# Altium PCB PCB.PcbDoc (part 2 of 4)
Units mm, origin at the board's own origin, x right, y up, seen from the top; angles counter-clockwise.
Board outline 114 x 86.5 mm, 4 copper layers (TOP, GND, SIG, BOTTOM), stack 1.586 mm thick; 98 components, 195 nets, 719 pads, 522 vias.
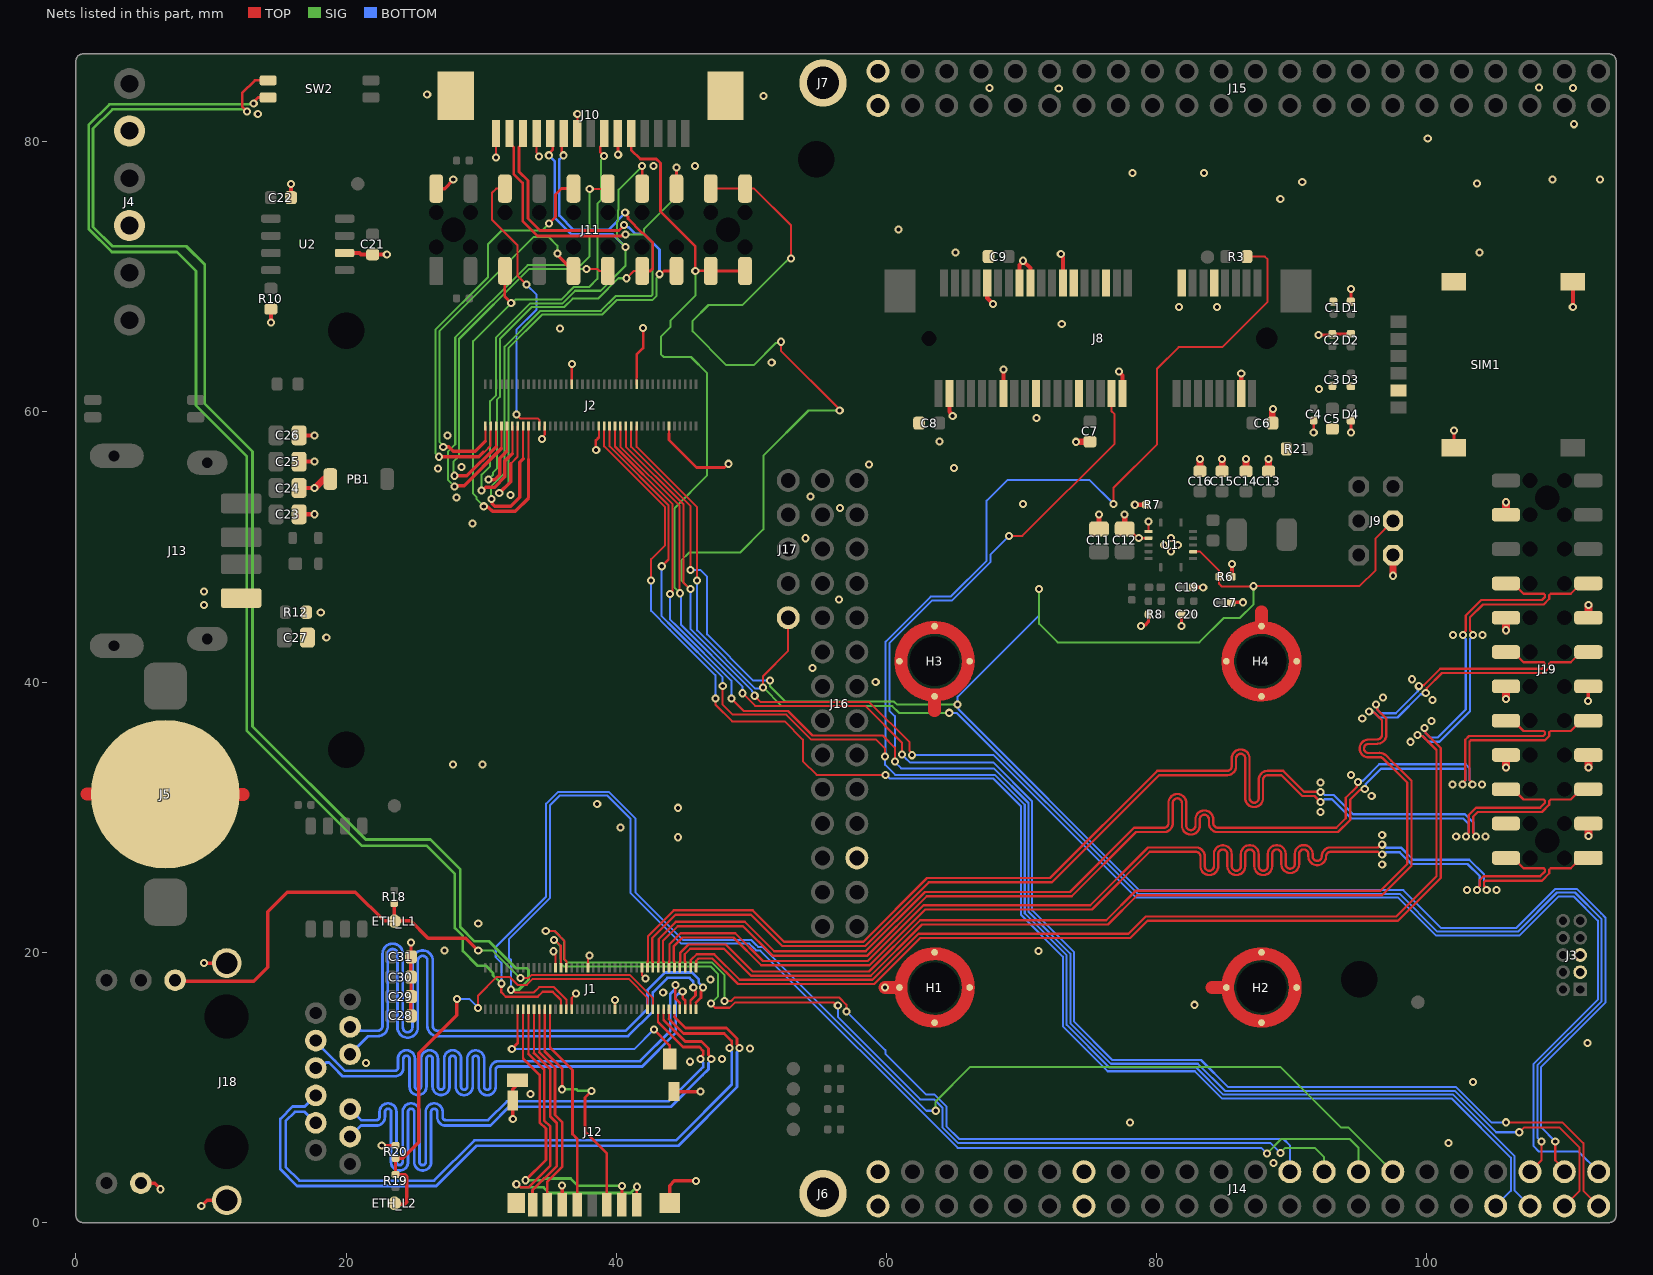
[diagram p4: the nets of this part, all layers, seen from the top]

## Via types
v1: diameter 0.6, hole 0.3, TOP to BOTTOM, tented both sides, 522 vias

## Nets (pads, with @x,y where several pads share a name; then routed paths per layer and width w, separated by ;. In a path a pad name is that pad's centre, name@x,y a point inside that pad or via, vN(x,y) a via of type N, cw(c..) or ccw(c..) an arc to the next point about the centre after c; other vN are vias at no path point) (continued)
CAM.CK_1_P: J2.18 J10.9 J11.5 | length 46.6
  TOP w0.15: 33.5,56.506 J2.18@33.5,58.96
  TOP w0.2: J11.5@31.75,70.435 31.75,68.529 v1(32.218,68.061) ; v1(39.078,78.953) 39.078,78.962 38.8,79.24 38.8,79.605 39.1,79.905 J10.9@39.1,80.6
  TOP w0.25: v1(30.185,53.018) 30.252,52.951 30.528,52.951 30.832,52.647 32.516,52.647 33.5,53.631 33.5,56.506
  SIG w0.15: v1(30.185,53.018) 29.633,53.57 29.633,53.722 29.404,53.951 29.404,65.247 v1(32.218,68.061) 32.264,68.061 32.524,68.321 35.908,68.321 36.837,69.25 38,69.25 38.6,69.849 38.6,75.425 38.852,75.678 38.852,78.64 39.078,78.866 v1(39.078,78.953)
CAM.D0_1_N: J2.16 J10.2 J11.16 | length 61
  TOP w0.15: 33.1,56.548 J2.16@33.1,58.96
  TOP w0.2: J10.2@32.1,80.6 32.1,79.905 32.4,79.605 32.4,77.617 33.062,76.955 33.062,74.148 34.178,73.032 40.359,73.032 40.386,73.059 40.603,73.059 v1(40.677,73.132) ; J11.16@44.45,76.535 44.454,76.539 44.454,78.095 v1(44.457,78.099)
  TOP w0.25: v1(30.749,53.57) 30.816,53.503 30.816,53.196 30.988,53.024 32.18,53.024 32.838,53.682 32.838,56.286 33.1,56.548
  SIG w0.15: v1(30.749,53.57) 30.737,53.582 30.737,54.486 31.73,55.48 31.73,64.833 34.387,67.49 38.851,67.49 39.936,68.574 42.566,68.574 42.687,68.696 42.687,72.502 42.054,73.135 ; v1(40.677,73.132) 40.68,73.135 42.054,73.135 ; v1(44.457,78.099) 44.457,75.957 42.054,73.554 42.054,73.135
CAM.D0_1_P: J2.14 J10.3 J11.15 | length 51.7
  TOP w0.15: 32.175,56.176 32.7,56.701 J2.14@32.7,58.96
  TOP w0.2: J10.3@33.1,80.6 33.1,79.905 32.8,79.605 32.8,77.783 33.462,77.121 33.462,74.313 34.344,73.432 40.196,73.432 40.568,73.804 v1(40.568,73.851) ; v1(43.196,70.196) 43.283,70.196 43.522,70.435 J11.15@44.45,70.435
  TOP w0.25: v1(31.333,54.002) 32.175,54.844 32.175,56.176
  SIG w0.15: v1(31.333,54.002) 32.007,54.677 32.007,64.718 34.502,67.213 38.966,67.213 40.05,68.297 42.68,68.297 42.964,68.581 42.964,69.883 43.196,70.115 v1(43.196,70.196)
  BOTTOM w0.2: v1(40.568,73.851) 40.676,73.851 40.865,73.662 40.926,73.662 41.402,73.187 42.038,73.187 43.202,72.022 43.202,70.202 v1(43.196,70.196)
CAM.D1_1_N: J2.12 J10.5 J11.14 | length 52.4
  TOP w0.15: 32.303,56.921 J2.12@32.303,58.946
  TOP w0.2: v1(35,79) 35.077,79.077 35.077,79.195 35.298,79.417 35.298,79.707 35.1,79.905 J10.5@35.1,80.6 ; J11.14@41.91,76.535 v1(41.91,78.2)
  TOP w0.25: v1(30.021,54.201) 30.108,54.201 30.347,54.44 30.99,54.44 31.752,55.202 31.752,56.369 32.303,56.921
  SIG w0.15: v1@30.031,54.21 30.031,55.357 30.657,55.983 30.657,60.797 31.1,61.24 31.1,65.515 33.629,68.044 36.023,68.044 36.952,68.973 38.833,68.973 40.676,70.816 v1(40.676,72.215) 40.066,72.826 40.066,74.059 40.122,74.115 40.122,74.931 40.174,74.984 40.174,76.464 v1(41.91,78.2)
  BOTTOM w0.2: v1(35,79) 35.434,78.566 35.434,74.387 36.685,73.135 39.756,73.135 v1(40.676,72.215)
CAM.D1_1_P: J2.10 J10.6 J11.13 | length 46.2
  TOP w0.15: 31.9,57.103 J2.10@31.9,58.96 ; v1(40.759,69.898) 41.296,70.435 J11.13@41.91,70.435
  TOP w0.2: v1(36.1,79) 36.1,79.108 35.953,79.256 35.953,80.453 J10.6@36.1,80.6 ; v1(40.656,74.755) 40.656,74.647 40.856,74.447 40.856,74.308 41.903,73.261 41.963,73.261 42.687,72.537 42.687,70.602 42.52,70.435 J11.13@41.91,70.435
  TOP w0.25: v1(30.533,54.992) 31.009,54.992 31.375,55.358 31.375,56.578 31.9,57.103
  SIG w0.15: v1(30.533,54.992) 30.533,55.017 30.853,55.337 30.853,55.496 31.159,55.802 31.159,60.907 31.377,61.125 31.377,65.401 33.743,67.767 36.138,67.767 36.764,68.393 38.645,68.393 40.15,69.898 v1(40.759,69.898)
  BOTTOM w0.2: v1(36.1,79) 35.784,78.684 35.784,74.532 36.83,73.485 39.406,73.485 40.656,74.735 v1(40.656,74.755)
CAM.D2_1_N: J2.8 J11.12 | length 36.5
  TOP w0.15: 31.5,57.303 J2.8@31.5,58.96 ; v1(38.029,76.49) 39.324,76.49 J11.12@39.37,76.535
  TOP w0.25: v1(28.029,54.473) 28.096,54.54 28.737,54.54 31.5,57.303
  SIG w0.15: v1(28.029,54.473) 27.527,54.975 27.527,57.05 28.076,57.599 28.076,65.517 33.429,70.87 37.372,70.87 38.029,71.528 v1(38.029,76.49)
CAM.D2_1_P: J2.6 J11.11 | length 29.1
  TOP w0.15: 31.1,57.436 J2.6@31.1,58.96 ; v1(37.805,70.593) 38.597,70.593 38.755,70.435 J11.11@39.37,70.435
  TOP w0.25: v1(28.029,55.28) 28.944,55.28 31.1,57.436
  SIG w0.15: v1(28.029,55.28) 27.943,55.366 27.943,55.586 27.937,55.593 27.937,56.305 28.353,56.722 28.353,65.403 33.544,70.593 v1(37.805,70.593)
CAM.D3_1_N: J2.4 J11.10 | length 32.1
  TOP w0.15: 30.159,57.028 30.211,57.028 30.7,57.517 J2.4@30.7,58.96
  TOP w0.2: v1(35.029,73.959) 35.5,74.43 35.5,76.1 35.935,76.535 J11.10@36.83,76.535
  TOP w0.25: v1(26.887,56.685) 29.816,56.685 30.159,57.028
  SIG w0.15: v1(26.887,56.685) 26.61,56.962 26.61,66.076 30.5,69.966 30.5,72.41 31.521,73.432 34.502,73.432 v1(35.029,73.959)
CAM.D3_1_P: J2.2 J11.9 | length 27.6
  TOP w0.15: 30.3,57.832 J2.2@30.3,58.96
  TOP w0.25: v1(27.188,57.42) 27.588,57.42 27.929,57.078 29.546,57.078 30.3,57.832 ; v1(35.634,71.717) 35.634,71.631 J11.9@36.83,70.435
  SIG w0.15: v1(27.188,57.42) 27.188,57.519 26.902,57.804 26.902,65.976 33.893,72.967 34.979,72.967 35.634,72.313 v1(35.634,71.717)
CAM.HS_1: J2.22 J11.6 | length 21.8
  TOP w0.15: J11.6@31.75,76.535 31.1,76.535 30.795,76.23 30.795,74.234 32.684,72.345 32.684,70.091 v1(33.353,69.423) ; v1(32.598,59.816) 32.896,59.518 33.648,59.518 33.65,59.516 34.194,59.516 34.3,59.41 J2.22@34.3,58.96
  BOTTOM w0.15: v1(32.598,59.816) 32.598,66.072 34.073,67.547 34.073,68.702 v1(33.353,69.423)
CAN0.RX_1: J1.52 J14.28 | length 71.8
  TOP w0.15: v1(35.372,20.926) 35.455,20.926 35.886,20.495 35.886,19.519 35.9,19.505 J1.52@35.9,18.86 ; v1(47,16.2) 47.302,15.898 48.388,15.898 48.792,16.302 56.074,16.302 56.32,16.056 v1(56.393,16.056)
  SIG w0.15: v1(35.372,20.926) 35.86,20.438 35.86,19.194 36.094,18.96 46.97,18.96 47.519,18.412 47.519,16.719 v1(47,16.2) ; v1(89.156,5.16) 89.52,5.524 91.694,5.524 92.394,4.824 J14.28@92.394,3.76
  BOTTOM w0.15: v1(56.393,16.056) 56.393,15.217 62.493,9.117 63.515,9.117 64.153,8.48 64.153,7.027 65.276,5.904 88.412,5.904 v1(89.156,5.16)
CAN0.TX_1: J1.50 J14.26 | length 70.8
  TOP w0.15: v1(34.773,21.585) 35.423,21.585 35.874,21.134 35.874,21.123 36.163,20.834 36.163,19.634 36.18,19.617 36.18,19.478 36.3,19.357 J1.50@36.3,18.86 ; v1(48,16.4) 48.498,16.4 48.739,16.641 56.518,16.641 57.03,16.129 v1(57.03,15.634)
  SIG w0.15: v1(34.773,21.585) 35.423,21.585 36.14,20.867 36.14,19.469 36.372,19.237 47.085,19.237 48.021,18.302 48.021,16.421 v1(48,16.4)
  BOTTOM w0.15: v1(57.03,15.634) 59.908,12.755 59.908,12.482 62.931,9.46 63.564,9.46 64.43,8.594 64.43,7.142 65.39,6.181 89.383,6.181 89.854,5.71 J14.26@89.854,3.76
CAN1.RX_1: J1.51 J14.32 SW2.2 | length 198.7
  TOP w0.15: 35.868,16.505 35.9,16.473 J1.51@35.9,15.78
  TOP w0.18: v1(31.487,17.677) 31.487,17.044 31.817,16.714 34.178,16.714 34.55,17.086 35.286,17.086 35.868,16.505
  TOP w0.2: v1(13.157,82.829) 13.234,82.905 13.234,83.026 13.482,83.274 SW2.2@14.217,83.274
  SIG w0.15: v1(63.642,8.274) 63.642,8.956 66.212,11.526 89.156,11.526 93.661,7.021 94.213,7.021 J14.32@97.474,3.76
  SIG w0.2: v1(13.157,82.829) 13.1,82.772 2.477,82.772 0.936,81.231 0.936,73.56 2.655,71.84 7.481,71.84 8.888,70.434 8.888,60.476 12.633,56.73 12.633,36.417 21.15,27.9 25.95,27.9 28.047,25.803 28.047,21.796 28.633,21.209 28.633,20.083 29.705,19.012 30.335,19.012 30.873,18.474 30.873,18.291 v1(31.487,17.677)
  BOTTOM w0.15: v1(31.487,17.677) 31.487,19.235 31.073,19.649 31.073,20.395 34.81,24.132 34.81,31.01 35.685,31.885 39.438,31.885 41.406,29.917 41.406,24.435 44.924,20.917 49.966,20.917 50.305,20.578 50.319,20.578 50.492,20.405 50.813,20.405 62.945,8.274 v1(63.642,8.274)
CAN1.TX_1: J1.49 J14.30 SW2.1 | length 198.2
  TOP w0.15: v1(32.195,17.231) 32.316,17.231 32.505,17.042 33.905,17.042 34.285,17.423 35.384,17.423 36.3,16.507 J1.49@36.3,15.78
  TOP w0.2: v1(12.66,82.245) 12.302,82.603 12.302,83.607 13.24,84.544 SW2.1@14.217,84.544
  SIG w0.15: v1(88.15,5.102) 89.228,6.181 94.277,6.181 94.934,5.524 J14.30@94.934,3.76
  SIG w0.2: v1(12.66,82.245) 12.552,82.245 12.395,82.402 2.697,82.402 1.264,80.968 1.264,73.694 2.69,72.268 8.164,72.268 9.536,70.896 9.536,60.597 13.075,57.059 13.075,36.725 21.45,28.35 26.229,28.35 28.448,26.13 28.448,21.856 29.489,20.816 30.592,20.816 32.592,18.816 33.383,18.816 33.5,18.699 33.5,17.953 32.778,17.231 v1(32.195,17.231)
  BOTTOM w0.15: v1(32.195,17.231) 32.195,19.465 32.044,19.615 32.044,20.974 35.1,24.03 35.1,30.908 35.8,31.608 39.323,31.608 41.063,29.869 41.063,24.387 44.809,20.64 49.851,20.64 50.19,20.301 50.204,20.301 50.377,20.128 50.66,20.128 65.264,5.524 87.728,5.524 v1(88.15,5.102)
CD: J1.67 J12.CD1 | length 16.9
  TOP w0.15: 32.7,13.664 J1.67@32.7,15.78
  TOP w0.2: v1(32.262,12.833) 32.7,13.272 32.7,13.664 ; v1(42.777,14.29) 43.95,13.117 J12.CD1@43.95,12.112
  BOTTOM w0.15: v1(32.262,12.833) 41.32,12.833 v1(42.777,14.29)
CLK: J1.55 J12.5 | length 15.3
  TOP w0.15: 35.1,12.953 J1.55@35.1,15.78
  TOP w0.2: 35.1,12.953 36.761,11.292 36.761,6.542 37.1,6.203 J12.5@37.1,1.312
CMD: J1.57 J12.3 | length 18
  TOP w0.15: 34.7,12.661 J1.57@34.7,15.78
  TOP w0.2: 34.7,12.661 36,11.361 36,9.88 v1(35.982,9.862) ; v1(38.175,9.75) 38.161,9.75 37.673,9.262 37.673,6.734 39.3,5.107 J12.3@39.3,1.312
  SIG w0.2: v1(35.982,9.862) 37.058,9.862 37.17,9.75 v1(38.175,9.75)
D0: J1.59 J12.7 | length 15.6
  TOP w0.15: 34.3,12.599 J1.59@34.3,15.78
  TOP w0.2: 34.3,12.599 35.455,11.444 35.455,7.954 36,7.408 36,4.134 34.876,3.01 34.876,1.336 J12.7@34.9,1.312
D1: J1.61 J12.8 | length 15.9
  TOP w0.15: 33.9,12.536 J1.61@33.9,15.78
  TOP w0.2: J12.8@33.8,1.312 33.8,2.396 35.597,4.193 35.597,7.35 35.115,7.831 35.115,11.321 33.9,12.536
D2: J1.63 J12.1 | length 26.3
  TOP w0.15: 33.5,12.474 J1.63@33.5,15.78
  TOP w0.2: v1(32.594,2.832) 32.697,2.832 32.928,2.601 33.506,2.601 35.115,4.209 35.115,7.093 34.653,7.555 34.653,11.321 33.5,12.474 ; J12.1@41.5,1.312 41.519,1.331 v1(41.519,2.649)
  SIG w0.2: v1(32.594,2.832) 32.697,2.832 32.928,2.601 34.606,2.601 35.019,2.188 41.058,2.188 v1(41.519,2.649)
D3: J1.65 J12.2 | length 22.8
  TOP w0.15: 33.1,12.153 J1.65@33.1,15.78
  TOP w0.2: 33.1,12.153 34.326,10.927 34.326,7.42 34.788,6.958 34.788,4.628 v1(33.288,3.128) ; J12.2@40.4,1.312 40.418,1.33 v1(40.418,2.715)
  SIG w0.2: v1(33.288,3.128) 34.541,3.128 34.671,3.258 36.616,3.258 37.16,2.715 v1(40.418,2.715)
DSI_CK_N: J1.20 J19.5 | length 90.9
  TOP w0.17: J1.20@42.3,18.86 42.3,19.324 42.34,19.364 42.34,21.193 44.254,23.106 50.096,23.106 52.41,20.792 58.293,20.792 62.999,25.498 72.106,25.498 80.041,33.433 84.971,33.433 85.216,33.433 ccw(c85.216,33.772) 85.555,33.772 85.555,34.363 cw(c86.214,34.363) 86.873,34.363 86.873,31.411 ccw(c87.212,31.411) 87.551,31.411 87.551,32.774 cw(c88.21,32.774) 88.21,33.433 89.365,33.433 90.912,31.886 91.102,31.886 92.096,31.886 v1(92.126,31.856) ; v1(103.624,28.561) 103.624,28.672 103.42,28.876 103.42,30.041 103.763,30.384 108.514,30.384 109.064,30.935 109.064,31.208 109.164,31.307 110.652,31.307 111.414,32.069 J19.5@111.954,32.069
  BOTTOM w0.17: v1(92.126,31.856) 92.237,31.856 92.44,31.653 93.107,31.653 94.53,30.23 102.823,30.23 103.42,29.633 103.42,28.881 103.624,28.678 v1(103.624,28.561)
DSI_CK_P: J1.18 J19.6 | length 90
  TOP w0.17: J1.18@42.7,18.86 42.7,19.324 42.66,19.364 42.66,21.06 44.386,22.786 49.963,22.786 52.277,20.472 58.426,20.472 63.131,25.178 72.238,25.178 80.173,33.113 84.971,33.113 85.216,33.113 ccw(c85.216,33.772) 85.875,33.772 85.875,34.363 cw(c86.214,34.363) 86.553,34.363 86.553,31.411 ccw(c87.212,31.411) 87.871,31.411 87.871,32.774 cw(c88.21,32.774) 88.21,33.113 89.232,33.113 90.779,31.566 91.102,31.566 91.689,31.566 92.015,31.24 92.015,31.129 v1(92.126,31.129) ; v1(102.897,28.561) 102.897,28.672 103.1,28.876 103.1,30.174 103.631,30.704 108.381,30.704 108.744,31.067 108.744,31.208 108.644,31.307 107.156,31.307 106.394,32.069 J19.6@105.854,32.069
  BOTTOM w0.17: v1(92.126,31.129) 92.237,31.129 92.44,31.333 92.975,31.333 94.397,29.91 102.69,29.91 103.1,29.5 103.1,28.881 102.897,28.678 v1(102.897,28.561)
DSI_D0_N: J1.16 J19.9 | length 90.9
  TOP w0.17: J1.16@43.1,18.86 43.1,19.324 43.14,19.364 43.14,20.993 44.406,22.259 49.509,22.259 51.69,20.078 58.452,20.078 62.847,24.473 73.579,24.473 78.328,29.222 80.287,29.222 80.532,29.222 ccw(c80.532,29.561) 80.871,29.561 80.871,31.059 cw(c81.53,31.059) 82.189,31.059 82.189,29.377 ccw(c82.528,29.377) 82.867,29.377 82.867,29.849 cw(c83.526,29.849) 84.185,29.849 84.185,29.561 ccw(c84.524,29.561) 84.524,29.222 85.985,29.222 93.292,29.222 94,29.931 94,31.44 94.807,32.248 94.807,32.536 v1(94.886,32.614) ; v1(103.36,32.417) 103.36,32.528 103.156,32.731 103.156,35.6 103.256,35.699 108.749,35.699 109.064,36.015 109.064,36.288 109.164,36.387 110.652,36.387 111.414,37.149 J19.9@111.954,37.149
  BOTTOM w0.17: v1(94.886,32.614) 94.964,32.693 95.252,32.693 96.48,33.92 102.87,33.92 103.157,33.633 103.157,32.731 103.36,32.528 v1(103.36,32.417)
DSI_D0_P: J1.14 J19.10 | length 89.8
  TOP w0.17: J1.14@43.5,18.86 43.5,19.324 43.46,19.364 43.46,20.86 44.539,21.939 49.377,21.939 51.558,19.758 58.584,19.758 62.979,24.153 73.711,24.153 78.46,28.902 80.287,28.902 80.532,28.902 ccw(c80.532,29.561) 81.191,29.561 81.191,31.059 cw(c81.53,31.059) 81.869,31.059 81.869,29.377 ccw(c82.528,29.377) 83.187,29.377 83.187,29.849 cw(c83.526,29.849) 83.865,29.849 83.865,29.561 ccw(c84.524,29.561) 84.524,28.902 85.985,28.902 93.424,28.902 94.32,29.798 94.32,31.308 95.034,32.021 95.321,32.021 v1(95.4,32.1) ; v1(102.633,32.417) 102.633,32.528 102.836,32.731 102.836,35.732 103.123,36.019 108.616,36.019 108.744,36.147 108.744,36.288 108.644,36.387 107.156,36.387 106.394,37.149 J19.10@105.854,37.149
  BOTTOM w0.17: v1(95.4,32.1) 95.479,32.179 95.479,32.466 96.612,33.6 102.737,33.6 102.837,33.5 102.837,32.731 102.633,32.527 v1(102.633,32.417)
DSI_D1_N: J1.12 J19.1 | length 90.9
  TOP w0.17: J1.12@43.9,18.86 43.9,19.324 43.94,19.364 43.94,20.593 44.759,21.411 48.807,21.411 50.858,19.361 58.607,19.361 62.734,23.488 75.077,23.488 79.356,27.767 81.653,27.767 82.896,27.767 cw(c82.896,27.108) 83.555,27.108 83.555,26.376 ccw(c83.894,26.376) 84.233,26.376 84.233,27.275 cw(c84.892,27.275) 85.551,27.275 85.551,26.377 ccw(c85.89,26.377) 86.229,26.377 86.229,27.276 cw(c86.888,27.276) 87.547,27.276 87.547,26.378 ccw(c87.886,26.378) 88.225,26.378 88.225,27.277 cw(c88.884,27.277) 89.543,27.277 89.543,26.529 ccw(c89.882,26.529) 90.221,26.529 90.221,27.278 cw(c90.88,27.278) 91.539,27.278 91.539,27.108 ccw(c91.878,27.108) 92.217,27.108 cw(c92.876,27.108) 92.876,27.767 96.376,27.767 ; 96.376,27.767 96.576,27.967 v1(96.691,27.967) ; v1(104.427,24.6) 104.427,24.711 104.223,24.915 104.223,25.205 104.323,25.304 108.514,25.304 109.064,25.855 109.064,26.128 109.164,26.227 110.652,26.227 111.414,26.989 J19.1@111.954,26.989
  BOTTOM w0.17: v1(96.691,27.967) 96.771,27.967 97.005,27.733 98.113,27.733 98.987,26.859 103.139,26.859 104.223,25.774 104.223,24.915 104.427,24.711 v1(104.427,24.6)
DSI_D1_P: J1.10 J19.2 | length 89.8
  TOP w0.15: J1.10@44.3,18.86 J1.10@44.301,18.861
  TOP w0.17: J1.10@44.3,18.86 44.3,19.324 44.26,19.364 44.26,20.46 44.891,21.091 48.675,21.091 50.725,19.041 58.74,19.041 62.867,23.168 75.209,23.168 79.488,27.447 81.654,27.447 82.896,27.447 cw(c82.896,27.108) 83.235,27.108 83.235,26.376 ccw(c83.894,26.376) 84.553,26.376 84.553,27.275 cw(c84.892,27.275) 85.231,27.275 85.231,26.377 ccw(c85.89,26.377) 86.549,26.377 86.549,27.276 cw(c86.888,27.276) 87.227,27.276 87.227,26.378 ccw(c87.886,26.378) 88.545,26.378 88.545,27.277 cw(c88.884,27.277) 89.223,27.277 89.223,26.529 ccw(c89.882,26.529) 90.541,26.529 90.541,27.278 cw(c90.88,27.278) 91.219,27.278 91.219,27.108 ccw(c91.878,27.108) 92.537,27.108 cw(c92.876,27.108) 92.876,27.447 96.376,27.447 ; 96.376,27.447 96.583,27.24 v1(96.691,27.24) ; v1(103.7,24.6) 103.7,24.711 103.904,24.915 103.904,25.337 104.191,25.624 108.381,25.624 108.744,25.987 108.744,26.128 108.644,26.227 107.156,26.227 106.394,26.989 J19.2@105.854,26.989
  BOTTOM w0.17: v1(96.691,27.24) 96.807,27.24 96.98,27.413 97.981,27.413 98.855,26.539 103.006,26.539 103.904,25.641 103.904,24.915 103.7,24.711 v1(103.7,24.6)
DSI_D2_N: J1.8 J19.13 | length 93.3
  TOP w0.17: J1.8@44.7,18.86 44.7,19.324 44.74,19.364 44.74,19.987 45.337,20.584 48.106,20.584 50.104,18.587 58.706,18.587 62.494,22.375 76.26,22.375 78.434,24.549 96.549,24.549 98.537,26.538 98.537,32.563 97.222,33.878 97.137,33.963 97.043,34.057 96.753,34.347 ccw(c96.512,34.108) 96.505,34.447 95.693,34.431 cw(c95.68,35.089) 95.021,35.076 cw(c95.68,35.089) 95.666,35.748 96.343,35.762 ccw(c96.335,36.101) 96.674,36.101 96.674,37.174 96.559,37.289 96.1,37.748 95.812,37.748 v1(95.73,37.83) ; v1(99.914,39.186) 99.993,39.264 99.993,39.552 101.114,40.674 108.643,40.674 109.064,41.095 109.064,41.368 109.164,41.467 110.652,41.467 111.414,42.229 J19.13@111.954,42.229
  BOTTOM w0.17: v1(95.73,37.83) 95.808,37.751 96.096,37.751 96.467,37.38 97.82,37.38 99.548,39.107 99.836,39.107 v1(99.914,39.186)
DSI_D2_P: J1.6 J19.14 | length 92.7
  TOP w0.17: J1.6@45.1,18.86 45.1,19.324 45.06,19.364 45.06,19.855 45.47,20.264 47.974,20.264 49.971,18.267 58.838,18.267 62.626,22.055 76.392,22.055 78.567,24.229 96.681,24.229 98.857,26.405 98.857,32.696 97.666,33.887 97.364,34.189 97.026,34.527 96.931,34.621 96.926,34.621 ccw(c96.512,34.108) 96.497,34.767 95.687,34.751 cw(c95.68,35.089) 95.341,35.082 cw(c95.68,35.089) 95.673,35.428 96.347,35.442 ccw(c96.335,36.101) 96.994,36.101 96.994,37.298 96.994,37.306 96.326,37.974 96.326,38.262 v1(96.244,38.344) ; v1(99.4,39.7) 99.479,39.779 99.766,39.779 100.982,40.994 108.511,40.994 108.744,41.227 108.744,41.368 108.644,41.467 107.156,41.467 106.394,42.229 J19.14@105.854,42.229
  BOTTOM w0.17: v1(96.244,38.344) 96.322,38.265 96.322,37.978 96.6,37.7 97.688,37.7 99.321,39.334 99.321,39.621 v1(99.4,39.7)
DSI_D3_N: J1.4 J19.17 | length 93.3
  TOP w0.17: J1.4@45.5,18.86 45.515,18.875 45.515,19.436 45.945,19.867 47.239,19.867 49.135,17.97 58.961,17.97 62.367,21.376 77.91,21.376 79.195,22.66 97.732,22.66 100.703,25.631 100.703,34.985 99.666,36.021 99.379,36.021 v1(99.3,36.1) ; v1(103.4,43.5) 103.4,43.611 103.197,43.815 103.197,44.797 104.154,45.754 108.643,45.754 109.064,46.175 109.064,46.448 109.164,46.547 110.652,46.547 111.414,47.309 J19.17@111.954,47.309
  BOTTOM w0.17: v1(99.3,36.1) 99.379,36.021 99.666,36.021 100.108,35.58 100.933,35.58 103.197,37.844 103.197,43.185 103.4,43.389 v1(103.4,43.5)
DSI_D3_P: J1.2 J19.18 | length 92.7
  TOP w0.17: J1.2@45.9,18.86 45.915,18.875 45.915,19.384 46.078,19.547 47.106,19.547 49.003,17.65 59.094,17.65 62.499,21.056 78.043,21.056 79.327,22.34 97.865,22.34 101.023,25.498 101.023,35.117 99.893,36.248 99.893,36.536 v1(99.814,36.614) ; v1(102.673,43.5) 102.673,43.611 102.877,43.815 102.877,44.929 104.021,46.074 108.511,46.074 108.744,46.307 108.744,46.448 108.644,46.547 107.156,46.547 106.394,47.309 J19.18@105.854,47.309
  BOTTOM w0.17: v1(99.814,36.614) 99.893,36.536 99.893,36.248 100.24,35.9 100.8,35.9 102.877,37.977 102.877,43.185 102.673,43.389 v1(102.673,43.5)
ETH_A_N: J1.3 J18.10 | length 54.1
  TOP w0.15: J1.3@45.5,15.78 45.5,16.449
  TOP w0.2: 45.5,16.449 45.86,16.809 45.86,17.135 45.695,17.3 v1(45.695,17.409)
  BOTTOM w0.2: J18.10@20.292,12.455 21.637,13.8 22.036,13.8 22.336,13.8 ccw(c22.336,14.554) 23.09,14.554 23.09,19.892 cw(c23.444,19.892) 23.798,19.892 23.798,14.435 ccw(c24.552,14.435) 25.306,14.435 25.306,19.387 cw(c25.66,19.387) 26.014,19.387 26.014,14.554 ccw(c26.768,14.554) 26.768,13.8 27.899,13.8 40.865,13.8 42.7,15.634 42.7,17.041 43.773,18.115 45.428,18.115 45.695,17.848 v1(45.695,17.409)
ETH_A_P: J1.1 J18.11 | length 54.4
  TOP w0.15: J1.1@45.9,15.78 45.9,16.283
  TOP w0.2: 45.9,16.283 46.26,16.643 46.26,17.14 46.422,17.302 v1(46.422,17.411)
  BOTTOM w0.2: J18.11@20.292,14.485 20.56,14.217 21.092,14.217 21.109,14.2 22.036,14.2 22.336,14.2 ccw(c22.336,14.554) 22.69,14.554 22.69,19.892 cw(c23.444,19.892) 24.198,19.892 24.198,14.435 ccw(c24.552,14.435) 24.906,14.435 24.906,19.387 cw(c25.66,19.387) 26.414,19.387 26.414,14.554 ccw(c26.768,14.554) 26.768,14.2 27.899,14.2 40.7,14.2 42.3,15.8 42.3,17.207 43.607,18.515 45.594,18.515 46.095,18.013 46.095,17.754 46.422,17.427 v1(46.422,17.411)
ETH_B_N: J1.7 J18.5 | length 54.5
  TOP w0.15: J1.7@44.7,15.78 44.7,16.254
  TOP w0.2: v1(44.365,17.573) 44.365,16.589 44.7,16.254
  BOTTOM w0.2: J18.5@17.752,13.47 17.752,13.23 17.91,13.23 19.187,11.953 19.915,11.225 20.958,11.225 23.609,11.225 ccw(c23.609,11.452) 23.836,11.452 23.836,12.126 cw(c24.463,12.126) 25.09,12.126 25.09,10.062 ccw(c25.317,10.062) 25.544,10.062 25.544,12.123 cw(c26.171,12.123) 26.798,12.123 26.798,10.06 ccw(c27.025,10.06) 27.252,10.06 27.252,12.121 cw(c27.879,12.121) 28.506,12.121 28.506,10.057 ccw(c28.733,10.057) 28.96,10.057 28.96,12.118 cw(c29.587,12.118) 30.214,12.118 30.214,10.055 ccw(c30.441,10.055) 30.668,10.055 30.668,11.318 cw(c31.295,11.318) 31.295,11.945 31.596,11.945 41.753,11.945 43.989,14.181 43.989,16.915 44.288,17.214 44.288,17.496 v1(44.365,17.573)
ETH_B_P: J1.5 J18.4 | length 53.9
  TOP w0.15: J1.5@45.1,15.78 45.1,16.42
  TOP w0.2: v1(44.913,17.095) 44.913,16.607 45.1,16.42
  BOTTOM w0.2: J18.4@17.752,11.44 17.752,11.68 18.371,11.68 18.53,11.839 18.735,11.839 19.021,11.553 19.749,10.825 20.958,10.825 23.609,10.825 ccw(c23.609,11.452) 24.236,11.452 24.236,12.126 cw(c24.463,12.126) 24.69,12.126 24.69,10.062 ccw(c25.317,10.062) 25.944,10.062 25.944,12.123 cw(c26.171,12.123) 26.398,12.123 26.398,10.06 ccw(c27.025,10.06) 27.652,10.06 27.652,12.121 cw(c27.879,12.121) 28.106,12.121 28.106,10.057 ccw(c28.733,10.057) 29.36,10.057 29.36,12.118 cw(c29.587,12.118) 29.814,12.118 29.814,10.055 ccw(c30.441,10.055) 31.068,10.055 31.068,11.318 cw(c31.295,11.318) 31.295,11.545 31.595,11.545 41.919,11.545 44.389,14.016 44.389,16.749 44.6,16.96 44.669,16.96 44.805,17.095 v1(44.913,17.095)
ETH_C_N: J1.11 J18.2 | length 52
  TOP w0.15: 43.9,15.062 J1.11@43.9,15.696
  TOP w0.2: 43.9,15.062 44.967,13.995 47.982,13.995 48.533,13.444 48.533,13.183 48.363,13.013 v1(48.363,12.905) ; J1.11@43.9,15.696 43.901,15.697 J1.11@43.901,15.779
  BOTTOM w0.2: J18.2@17.752,7.38 16.937,8.195 16.21,8.195 15.525,7.51 15.525,4.11 16.535,3.1 26.502,3.1 29.487,6.085 44.42,6.085 48.533,10.198 48.533,12.627 48.363,12.797 v1(48.363,12.905)
ETH_C_P: J1.9 J18.3 | length 54
  TOP w0.15: 44.3,15.228 J1.9@44.3,15.53
  TOP w0.198: J1.9@44.3,15.53 J1.9@44.3,15.78
  TOP w0.2: 44.3,15.228 45.133,14.395 48.148,14.395 48.933,13.61 48.933,13.183 49.103,13.013 v1(49.103,12.905)
  BOTTOM w0.2: J18.3@17.752,9.41 16.937,8.595 16.045,8.595 15.125,7.675 15.125,3.945 16.37,2.7 26.667,2.7 29.653,5.685 44.586,5.685 48.933,10.032 48.933,12.627 49.103,12.797 v1(49.103,12.905)
ETH_D_N: J1.15 J18.9 | length 53.2
  TOP w0.15: 43.1,14.834 J1.15@43.1,15.78
  TOP w0.2: 43.1,14.834 44.937,12.997 46.14,12.997 46.424,12.712 46.424,12.42 46.224,12.22 v1(46.224,12.112)
  BOTTOM w0.2: J18.9@20.292,8.395 21.107,7.58 21.945,7.58 22.245,7.58 ccw(c22.245,7.807) 22.472,7.807 22.472,8.195 cw(c23.099,8.195) 23.726,8.195 23.726,4.473 ccw(c23.953,4.473) 24.18,4.473 24.18,8.195 cw(c24.807,8.195) 25.434,8.195 25.434,4.473 ccw(c25.661,4.473) 25.888,4.473 25.888,8.195 cw(c26.515,8.195) 27.142,8.195 27.142,7.807 ccw(c27.369,7.807) 27.369,7.58 28.778,7.58 30.507,7.58 31.898,8.972 43.874,8.972 46.214,11.312 46.224,11.312 46.424,11.512 46.424,11.804 46.224,12.004 v1(46.224,12.112)
ETH_D_P: J1.13 J18.8 | length 53.9
  TOP w0.15: 43.5,15 J1.13@43.5,15.78
  TOP w0.2: 43.5,15 45.103,13.397 46.305,13.397 46.824,12.878 46.824,12.42 47.024,12.22 v1(47.024,12.112)
  BOTTOM w0.2: J18.8@20.292,6.365 21.107,7.18 21.945,7.18 22.245,7.18 ccw(c22.245,7.807) 22.872,7.807 22.872,8.195 cw(c23.099,8.195) 23.326,8.195 23.326,4.473 ccw(c23.953,4.473) 24.58,4.473 24.58,8.195 cw(c24.807,8.195) 25.034,8.195 25.034,4.473 ccw(c25.661,4.473) 26.288,4.473 26.288,8.195 cw(c26.515,8.195) 26.742,8.195 26.742,7.807 ccw(c27.369,7.807) 27.369,7.18 28.778,7.18 30.673,7.18 32.064,8.572 44.039,8.572 46.38,10.912 46.39,10.912 46.824,11.346 46.824,11.804 47.024,12.004 v1(47.024,12.112)
ETH_L1: ETH_L1.X J1.17 J18.15 R18.1 | length 46.1
  TOP w0.15: v1(32.891,18.09) 33.485,18.09 33.703,18.308 37.284,18.308 39.266,18.308 40.884,18.308 41.019,18.308 42.7,16.627 J1.17@42.7,15.78
  TOP w0.25: J18.15@7.342,17.935 7.424,17.853 13.153,17.853 14.2,18.9 14.2,23.014 15.634,24.447 20.689,24.447 22.807,22.329 ETH_L1.X@23.556,22.329 ; R18.1@23.556,23.627 ETH_L1.X@23.556,22.329 ; ETH_L1.X@23.578,22.305 23.556,22.327 ETH_L1.X@23.556,22.329 ; ETH_L1.X@23.578,22.329 24.771,22.329 26.058,21.042 28.858,21.042 v1(29.777,20.123)
  SIG w0.15: v1(29.777,20.123) 30.858,20.123 v1(32.891,18.09)
ETH_L2: ETH_L2.X J1.19 R19.2 R20.1 | length 36.7
  TOP w0.15: v1(29.771,15.888) 29.771,16.804 31.146,18.179 32.092,18.179 32.683,17.588 33.375,17.588 33.818,18.031 37.398,18.031 39.151,18.031 40.904,18.031 42.3,16.635 J1.19@42.3,15.78
  TOP w0.25: ETH_L2.X@23.578,1.425 23.647,1.355 24.343,1.355 24.489,1.502 24.489,3.408 24.343,3.554 R19.2@23.657,3.554 R20.1@23.657,4.754 ; R20.1@23.664,4.754 24.206,4.754 25.379,5.928 25.379,12.52 28.2,15.341 v1(28.2,16.55)
  BOTTOM w0.15: v1(28.2,16.55) 29.109,16.55 v1(29.771,15.888)
GND: C1.1 C2.1 C3.1 C4.1 C5.1 C6.1 C7.1 C8.1 C9.2 C11.1 C12.1 C13.1 C14.1 C15.1 C16.1 C17.2 C19.1 C20.1 C21.2 C22.2 C23.1 C24.1 C25.1 C26.1 C27.1 C28.2 C29.2 C30.2 C31.2 D1.A D2.A D3.A D4.A H1.1 H2.1 H3.1 H4.1 J1.22 J1.31 J1.42 J1.47 J1.54 J2.24 J2.33 J2.44 J2.57 J2.70 J3.3 J3.5 J4.2 J4.4 J5.3 J6.1 J7.1 J8.4 J8.9 J8.15 J8.18 J8.21 J8.26 J8.27 J8.29 J8.34 J8.35 J8.37 J8.40 J8.43 J8.50 J9.6 J10.1 J10.4 J10.7 J10.10 J10.FIX J11.2 J12.6 J12.CD2 J12.SH1 J12.SH2 J12.SH3 J12.SH4 J13.4 J14.1 J14.2 J14.13 J14.14 J15.1 J15.2 J16.24 J18.13 J18.SH1 J18.SH2 J19.3 J19.4 J19.7 J19.8 J19.11 J19.12 J19.15 J19.16 J19.22 PB1.1 R6.1 R7.1 R8.1 R10.1 R12.1 R20.2 R21.1 SIM1.C5 SIM1.G1 SIM1.G2 SIM1.G4 U1.2 U1.3 U1.15 U2.2 | length 125.4
  TOP w0.15: v1(31.1,78.832) J10.1@31.1,80.6 ; J10.4@34.1,80.6 34.1,79.2 34.276,79.024 v1(34.276,78.902) ; v1(34.508,58.011) 34.508,58.132 34.7,58.324 J2.24@34.7,58.96 ; v1(35.358,20.08) 35.358,19.959 35.5,19.816 J1.54@35.5,18.86 ; J1.47@36.7,15.78 36.7,16.631 v1(37.009,16.94) ; J2.33@36.7,62.04 36.7,63.543 v1(36.712,63.555) ; J10.7@37.1,80.6 37.11,80.61 v1(37.11,82.042) ; J1.42@37.897,18.863 37.9,18.865 37.9,19.513 38.022,19.635 v1(38.022,19.757) ; 38.7,58.108 J2.44@38.7,58.96 ; J1.31@39.9,15.78 39.907,15.787 39.907,16.479 v1(39.914,16.486) ; J2.57@41.5,62.04 41.5,62.588 ; J1.22@41.9,18.86 41.9,18.3 v1(42.15,18.05) ; 43.9,58.395 J2.70@43.9,58.96 ; U1.2@79.399,51.159 v1(79.399,51.882)
  TOP w0.2: C23.1@16.505,52.428 C23.1@16.514,52.418 ; C24.1@16.505,54.378 C24.1@16.514,54.368 ; C25.1@16.505,56.328 C25.1@16.514,56.318 ; C26.1@16.514,58.268 C26.1@16.523,58.259 ; v1(38.511,57.192) 38.484,57.219 38.484,57.892 38.7,58.108 ; 41.5,62.588 41.5,64.238 41.984,64.721 v1(41.984,66.215) ; 43.9,58.395 43.9,57.928 45.945,55.883 48.012,55.883 48.294,56.164 v1(48.296,56.164) ; C12.1@77.627,51.341 77.888,51.341 78.57,50.658 v1(78.67,50.658) U1.3@79.399,50.659 ; v1(91.622,58.48) C4.1@91.622,59.38 ; v1(91.98,65.698) 93,65.698 93.072,65.771 D2.A@94.376,65.771 ; D1.A@94.361,68.156 D1.A@94.376,68.171 ; D1.A@94.376,68.171 v1(94.375,69.094) ; v1(94.376,58.465) D4.A@94.376,59.365
  TOP w0.25: J18.13@4.802,2.915 5.82,2.915 v1(6.27,2.465) ; v1@9.258,1.201 v1(9.276,1.219) 9.702,1.645 J18.SH2@11.152,1.645 ; v1@9.42,19.15 v1(9.475,19.205) J18.SH1@11.152,19.205 ; v1(22.636,5.704) R20.2@23.657,5.704 ; C28.2@24.795,15.288 24.795,16.718 C29.2@24.8,16.723 24.8,18.163 C30.2@24.795,18.167 24.795,19.664 C31.2@24.8,19.669 v1(24.8,20.726) v1@24.795,20.731 ; J11.2@26.67,76.535 27.285,76.535 27.929,77.179 v1(27.929,77.204) ; v1(32.335,7.649) 32.335,9.027 J12.SH4@32.325,9.037 32.325,9.862 32.698,10.235 J12.CD2@32.698,10.537 ; J12.SH1@32.595,1.445 J12.SH1@32.6,1.44 ; v1(35.982,2.731) 35.991,2.722 35.991,1.321 J12.6@36,1.312 ; J10.10@40.1,80.6 40.119,80.581 40.119,79.062 v1(40.138,79.043) ; J12.SH2@43.95,1.44 43.95,2.734 44.295,3.079 45.747,3.079 v1@45.782,3.114 ; J12.SH3@44.275,9.687 v1(46.224,9.687) ; v1(78.837,44.159) 78.904,44.226 79.158,44.226 79.39,44.458 R8.1@79.39,45.012 ; R7.1@79.187,53.138 R7.1@79.199,53.127 ; v1(81.834,44.146) C20.1@81.834,45.013 ; C19.1@82.704,47.025 82.708,47.021 83.438,47.021 v1(83.442,47.016) ; C17.2@85.357,45.911 85.365,45.903 86.391,45.903 v1(86.399,45.911) ; SIM1.G1@101.994,57.35 102.003,57.359 v1(102.003,58.637) ; v1(111.934,38.592) 111.934,39.67 J19.11@111.954,39.689 ; R8.1@79.389,45.013 R8.1@79.39,45.012
  TOP w0.3: v1(14.43,66.623) R10.1@14.43,67.606 ; C22.2@15.917,75.866 v1(15.917,76.88) ; C23.1@16.505,52.428 v1(17.655,52.428) ; C24.1@16.505,54.378 v1(17.655,54.378) ; C25.1@16.505,56.328 v1(17.655,56.328) ; C26.1@16.514,58.268 v1(17.664,58.268) ; U2.2@19.882,71.765 20.998,71.765 21.109,71.653 21.846,71.653 21.853,71.646 23.005,71.646 v1(23.009,71.643) ; J8.50@64.656,61.35 64.656,60.015 64.898,59.773 v1(64.898,59.692) ; J8.43@67.456,69.55 67.456,68.428 v1(67.882,68.002) ; J8.40@68.656,61.35 v1(68.656,63.15) ; J8.37@69.856,69.55 69.856,70.869 70.098,71.112 v1(70.098,71.192) 70.641,70.65 70.656,70.65 J8.35@70.656,69.55 ; v1(72.898,71.692) 72.898,71.611 73.065,71.445 J8.29@73.065,69.559 ; v1(77.198,62.992) 77.198,62.942 77.456,62.684 J8.18@77.456,61.35 ; v1(78.376,53.133) 78.379,53.13 79.179,53.13 R7.1@79.187,53.138 ; R6.1@85.565,47.8 v1(85.565,48.759) ; J8.4@86.256,61.35 v1(86.256,62.85) ; SIM1.G4@110.794,69.65 110.798,69.646 v1(110.798,67.783)
  TOP w0.4: C11.1@75.724,51.341 v1(75.724,52.399) ; C12.1@77.627,51.341 v1(77.627,52.399)
  TOP w0.5: v1(17.655,54.378) 17.674,54.397 17.732,54.397 18.37,55.035 PB1.1@18.829,55.035 ; v1(74.022,57.791) 74.028,57.798 75,57.798 C7.1@75.051,57.849 ; C16.1@83.205,55.61 v1(83.205,56.518) ; C15.1@84.842,55.61 v1(84.842,56.518) ; C14.1@86.608,55.61 v1(86.608,56.518) ; C13.1@88.275,55.61 v1(88.275,56.518) ; C6.1@88.576,59.176 88.558,59.194 88.558,60.154 88.61,60.205 v1(88.61,60.232) ; v1(97.49,47.877) J9.6@97.49,49.401
  TOP w0.6: v1(105.849,53.317) 105.854,53.311 J19.22@105.854,52.389 ; J19.8@105.854,34.609 105.854,33.688 v1(105.86,33.682) ; J19.12@105.854,39.689 105.854,38.768 v1(105.86,38.762) ; J19.16@105.854,44.769 105.854,43.848 v1(105.86,43.842) ; v1(111.949,45.697) 111.954,45.691 J19.15@111.954,44.769 ; J19.3@111.954,29.529 111.954,28.608 v1(111.96,28.602) ; J19.7@111.954,34.609 111.954,33.688 v1(111.96,33.682)
  TOP w0.95: 0.812,31.712 J5.3@6.618,31.712 ; J5.3@6.582,31.688 12.388,31.688 ; v1(59.897,17.397) H1.1@60.956,17.397 ; 63.556,37.888 H3.1@63.556,38.947 ; 84.097,17.397 H2.1@85.156,17.397 ; H4.1@87.756,44.147 87.756,45.206
  other v1: 45.896,3.07 88.646,4.4 101.6,5.9 78.016,7.39 33.65,9.501 103.4,10.4 21.464,11.798 45.455,11.904 47.832,12.112 49.898,12.892 111.9,13.3 82.8,16.118 43.47,17.038 46.971,18.003 27.273,20.123 71.25,20.1 29.778,22.141 102.973,24.6 105.154,24.6 96.691,26.513 44.55,28.518 102.17,28.561 104.35,28.561 96.691,28.694 40.303,29.228 92.126,30.402 44.55,30.699 38.585,30.985 95.914,31.586 101.906,32.417 104.087,32.417 92.126,32.583 94.372,33.128 27.923,33.9 30.104,33.9 98.786,35.586 100.328,37.128 95.216,37.316 100.428,38.672 96.758,38.858 59.2,40 98.886,40.214 54.515,41.056 18.53,43.3 101.946,43.5 104.127,43.5 18.121,45.144 9.48,45.7 56.487,46.114 9.48,46.7 81.049,49.659 80.543,50.153 81.555,50.153 53.988,50.652 81.049,50.659 29.347,51.751 56.542,52.899 70.098,53.192 28.177,53.665 54.367,53.752 32.162,53.857 26.813,55.816 64.981,55.862 28.541,55.923 58.701,56.107 63.91,57.81 27.49,58.251 71.1,59.55 92,61.698 51.5,63.66 35.837,66.173 72.972,66.524 81.644,67.76 84.458,67.76 65.095,71.791 103.897,71.794 60.9,73.5 89.148,75.763 103.7,76.9 90.773,77.023 109.3,77.2 112.8,77.2 78.2,77.7 83.498,77.692 42.737,78.2 45.832,78.2 100.064,80.238 110.9,81.3 13.458,82.051 50.9,83.4 26,83.5 72.749,83.944 67.631,83.982 110.821,83.987 108.31,84.025
GPIO1_1: J2.48 J14.39 R3.1 | length 169.6
  TOP w0.15: J2.48@39.497,58.957 39.497,57.458 43.862,53.093 43.862,49.08 v1(43.36,48.578) ; v1(47.875,39.704) 47.875,38.339 48.625,37.589 52.589,37.589 54.429,35.749 59.226,35.749 59.883,35.092 59.883,34.507 v1(59.898,34.492) ; v1(76.798,53.192) 76.798,54.385 80.037,57.624 80.037,63.215 81.623,64.801 84.85,64.801 88.213,68.164 88.213,71.299 88.012,71.5 R3.1@86.675,71.5
  BOTTOM w0.15: v1(43.36,48.578) 43.36,44.881 44.234,44.006 ; 44.234,44.006 47.875,40.365 v1(47.875,39.704) ; v1(76.798,53.192) 75.032,54.958 68.943,54.958 67.412,53.428 67.412,49.002 64.736,46.326 63.269,46.326 59.94,42.997 59.94,34.653 59.898,34.611 59.898,33.883 60.637,33.144 68.026,33.144 70.231,30.939 70.231,22.885 73.327,19.79 73.327,14.637 76.488,11.476 82.936,11.476 84.938,9.474 101.936,9.474 106.497,4.913 106.497,2.357 J14.39@107.634,1.22
GPIO2_1: J2.50 J8.20 J14.41 | length 149.7
  TOP w0.15: J2.50@39.9,58.96 39.9,57.446 44.143,53.203 44.143,46.709 43.963,46.529 v1(43.963,46.525) ; v1(48.516,38.79) 49.44,37.866 52.704,37.866 54.518,36.051 59.711,36.051 60.614,35.149 v1(60.614,34.113) ; v1(69.078,50.832) 70.061,50.832 76.887,57.659 76.887,59.834 76.656,60.066 J8.20@76.656,61.35 ; v1(106.837,6.682) 107.193,7.038 109.812,7.038 111.302,5.548 111.302,2.348 J14.41@110.174,1.22
  BOTTOM w0.15: v1(43.963,46.525) 43.963,44.669 44.511,44.121 ; 44.511,44.12 48.516,40.115 v1(48.516,38.79) ; v1@60.614,34.08 61.077,33.617 67.945,33.617 70.508,31.054 70.508,23 73.604,19.904 73.604,14.752 76.603,11.753 83.051,11.753 85.053,9.751 102.05,9.751 105.119,6.682 v1(106.837,6.682) ; v1(60.614,34.113) 60.614,37.483 60.217,37.88 60.217,42.882 63.383,46.049 64.851,46.049 67.689,48.887 67.689,49.443 v1(69.078,50.832)
GPIO3_1: J2.52 J10.11 J11.17 J11.19 J14.43 | length 158.2
  TOP w0.15: J2.52@40.3,58.96 40.3,57.438 44.691,53.047 44.691,46.598 v1(44.707,46.582) v1@44.707,46.504 ; v1(49.349,39.178) 50.28,38.246 58.42,38.246 61.132,35.533 v1(61.132,34.655) ; v1(105.845,7.419) 110.031,7.419 111.579,5.871 111.579,2.355 J14.43@112.714,1.22
  TOP w0.2: J10.11@41.1,80.6 41.1,79.4 41.773,78.727 42.955,78.727 43.264,78.418 43.264,74.843 45.844,72.263 v1(45.844,70.443) 46.982,70.443 J11.17@46.99,70.435 J11.19@49.53,70.435
  SIG w0.15: v1(44.707,46.582) 44.311,46.978 44.311,52.889 46.726,55.304 46.726,56.686 46.716,56.696 46.716,57.112 46.726,57.123 46.726,62.869 45.527,64.067 43.51,64.067 43.297,64.28 43.297,65.581 44.021,66.304 44.021,66.778 45.852,68.609 45.852,70.435 v1(45.844,70.443)
  BOTTOM w0.15: v1(44.707,46.582) 44.788,46.501 44.788,44.235 49.349,39.674 v1(49.349,39.178) ; v1(61.132,34.655) 61.396,34.391 61.396,34.384 61.721,34.059 67.894,34.059 70.785,31.168 70.785,23.115 73.881,20.019 73.881,14.866 76.718,12.03 83.281,12.03 85.282,10.028 102.165,10.028 104.774,7.419 v1(105.845,7.419)
GPIO4_1: J2.54 J11.18 J11.20 J14.44 | length 176.9
  TOP w0.15: J2.54@40.7,58.96 40.7,57.43 44.974,53.156 44.974,47.369 45.457,46.886 v1(45.476,46.886) ; J11.18@46.99,76.535 J11.20@49.53,76.535 50.204,76.535 52.926,73.813 v1(52.926,71.368) ; v1(50.242,38.994) 50.242,38.975 50.69,38.527 58.735,38.527 61.71,35.552 61.71,34.903 61.898,34.714 v1(61.898,34.592) ; v1(52.181,65.199) 52.181,64.534 56.534,60.181 v1(56.534,60.111)
  SIG w0.15: v1(45.476,46.886) 44.807,47.555 44.807,49.021 45.385,49.6 49.174,49.6 50.886,51.312 50.886,56.771 54.226,60.111 v1(56.534,60.111) ; v1(52.181,65.199) 52.104,65.122 51.816,65.122 50.158,63.464 48.144,63.464 45.647,65.961 45.647,66.739 46.825,67.917 49.157,67.917 49.164,67.923 49.345,67.923 52.575,71.153 52.59,71.153 52.805,71.368 v1(52.926,71.368)
  BOTTOM w0.15: v1(45.476,46.886) 45.476,43.94 50.047,39.368 50.047,39.307 50.242,39.112 v1(50.242,38.994) ; v1(61.898,34.592) 67.93,34.592 78.477,24.046 97.877,24.046 100.662,21.262 106.859,21.262 109.747,24.15 110.85,24.15 112.65,22.35 112.65,16.5 107.896,11.746 107.896,5.654 108.3,5.25 111.224,5.25 J14.44@112.714,3.76
GPIO5_1: J2.56 J9.4 J14.42 R6.2 U1.10 | length 170
  TOP w0.15: J2.56@41.099,58.959 41.099,57.423 45.476,53.046 v1(45.476,48.316) ; U1.10@82.699,49.659 83.21,49.659 84.615,48.254 84.615,47.274 84.794,47.095 87.144,47.095 v1(87.15,47.101) 95.007,47.101 96.198,48.292 96.198,50.649 J9.4@97.49,51.941 ; v1(109.5,6) 109.5,4.602 110.174,3.928 J14.42@110.174,3.76
  SIG w0.15: v1(51.375,40.127) 51.375,39.698 52.508,38.566 60.548,38.566 60.764,38.349 v1(65.264,38.349) ; v1(71.298,46.892) 71.298,44.322 72.671,42.949 83.164,42.949 84.964,44.749 86.156,44.749 87.15,45.744 v1(87.15,47.101)
  BOTTOM w0.15: v1(45.476,48.316) 46.2,48.316 46.723,47.794 46.723,43.538 50.145,40.115 51.363,40.115 v1(51.375,40.127) ; v1(71.298,46.892) 71.298,44.958 65.264,38.923 v1(65.264,38.349) 65.332,38.282 65.332,37.975 78.706,24.6 98.249,24.6 101.033,21.816 106.629,21.816 109.518,24.704 111.079,24.704 112.903,22.88 113.204,22.579 113.204,16.271 108.45,11.517 108.45,7.05 v1(109.5,6)
GPIO6_1: J2.58 J14.40 J17.5 | length 122.3
  TOP w0.15: J2.58@41.5,58.96 41.5,57.413 45.978,52.935 v1(45.978,47.533) ; v1(50.861,39.613) 50.861,40.455 52.724,42.318 J17.5@52.724,44.769 ; J14.40@107.634,3.76 108.48,4.606 v1(108.48,5.986)
  SIG w0.15: v1(50.861,39.613) 52.247,38.227 60.426,38.227 60.92,37.733 v1(64.641,37.733)
  BOTTOM w0.15: v1(45.978,47.533) 45.978,43.829 50.261,39.546 50.795,39.546 v1(50.861,39.613) ; v1(64.641,37.733) 65.182,37.733 78.591,24.323 97.992,24.323 100.776,21.539 106.744,21.539 109.632,24.427 110.965,24.427 112.846,22.546 112.927,22.465 112.927,16.385 108.173,11.631 108.173,6.293 v1(108.48,5.986)
GPIO.0_1: J2.46 J14.37 | length 110.4
  TOP w0.15: J2.46@39.1,58.96 39.1,57.463 43.585,52.978 43.585,50.112 42.575,49.102 v1(42.575,47.533) ; v1(47.33,38.79) 47.33,38.347 48.574,37.103 52.457,37.103 53.813,35.746 53.813,34.147 54.823,33.137 v1(59.934,33.137)
  BOTTOM w0.15: v1(42.575,47.533) 42.575,45.274 43.957,43.892 47.33,40.518 v1(47.33,38.79) ; v1(59.934,33.137) 59.96,33.137 60.23,32.867 67.911,32.867 69.954,30.824 69.954,22.771 73.05,19.675 73.05,16.006 73.05,14.522 76.374,11.199 82.822,11.199 84.823,9.197 101.821,9.197 106.216,4.802 106.216,2.342 J14.37@105.094,1.22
